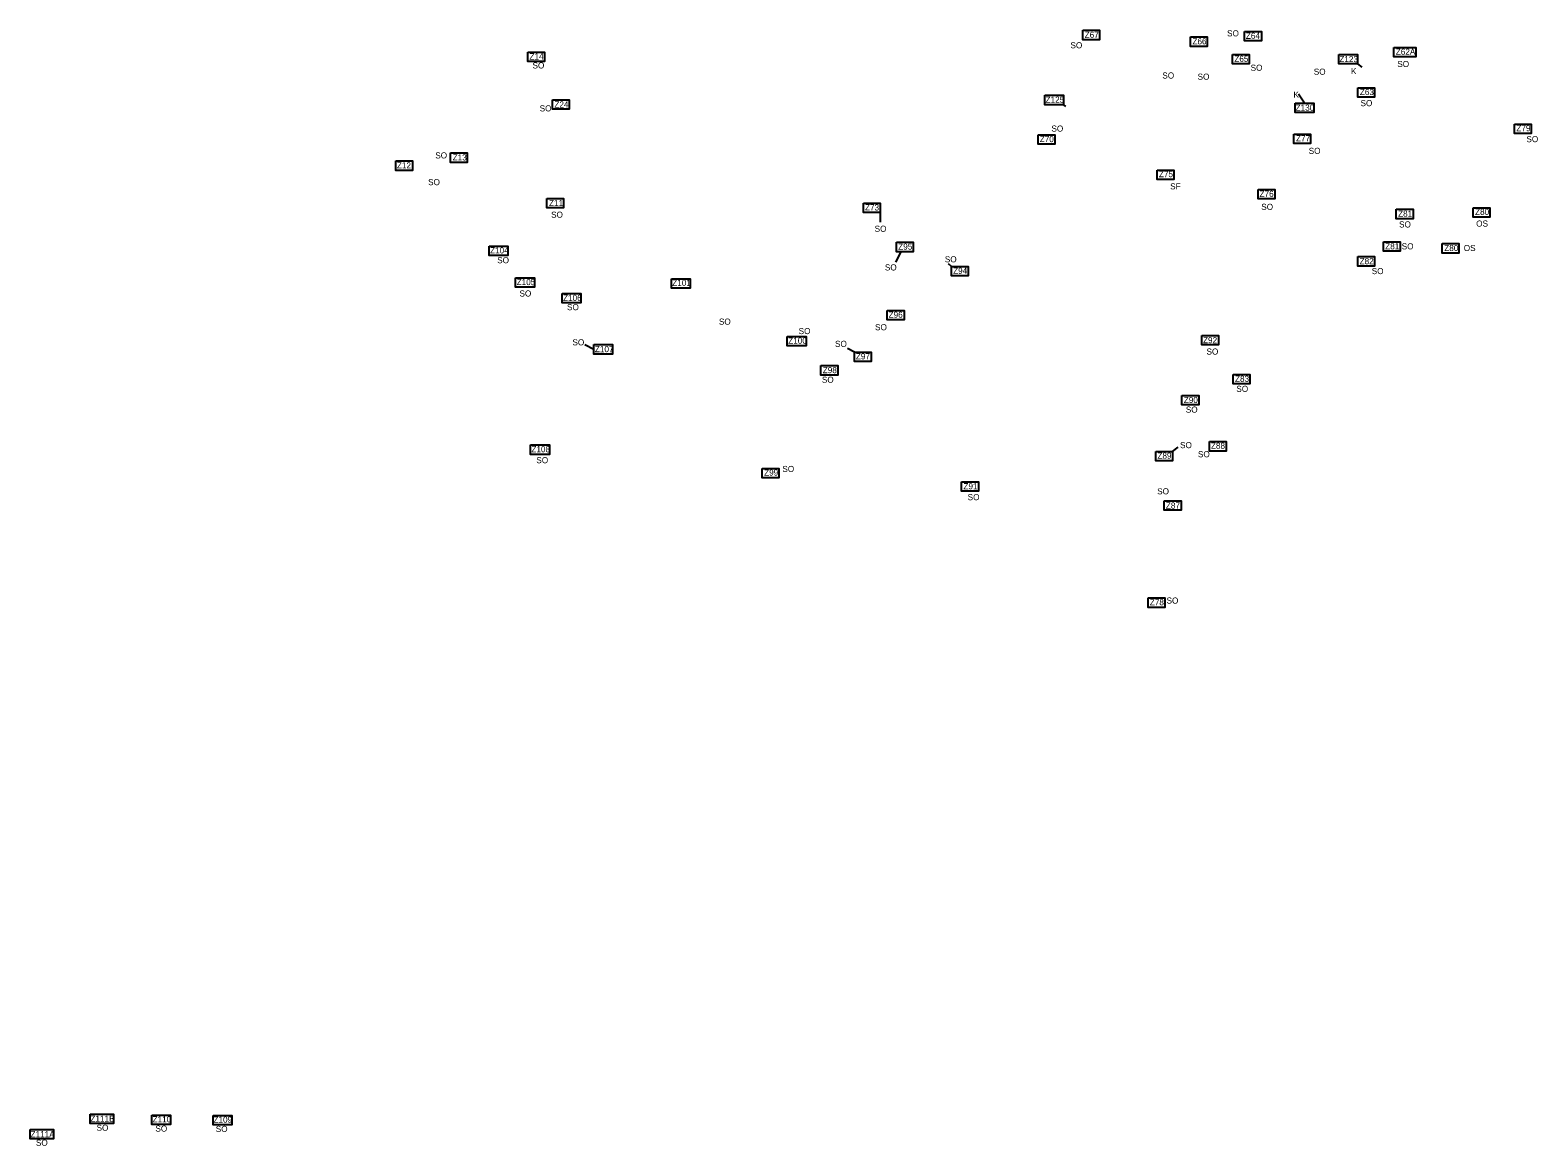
# Model space of a CAD drawing. Extents: x -443485 to -433023, y -1133480 to -1129775.
# Drawn here: x -443485 to -441021, y -1133480 to -1131657 of the extents above; entities that cross this region are included whole.
import ezdxf

# ---------------------------------------------------------------- set-up
doc = ezdxf.new("R2010")
doc.units = 0
for name, color, linetype in [('Vrstva 3', 7, 'Continuous'), ('Vrstva 4', 7, 'Continuous'), ('Vrstva 8', 7, 'Continuous')]:
    doc.layers.add(name, color=color, linetype=linetype)

msp = doc.modelspace()

# ---------------------------------------------------------------- linework, layer by layer
at = {"layer": 'Vrstva 3'}
for p, q in [((-441796.1, -1131778.7), (-441793, -1131781.3)), ((-442095.6, -1131954.7), (-442095.6, -1131970.4)), ((-442061.8, -1132018.8), (-442070.5, -1132035.8)), ((-441979.2, -1132043), (-441984, -1132038.5)), ((-442563.8, -1132178.3), (-442578.2, -1132171.1)), ((-442137.9, -1132182.9), (-442149.2, -1132176.8)), ((-441618.1, -1132344.9), (-441608.8, -1132338.2))]:
    msp.add_line(p, q, dxfattribs=at)
for points in [[(-441764.6, -1131657.1), (-441737.2, -1131657.1), (-441737.2, -1131672.5), (-441764.6, -1131672.5)], [(-441588.7, -1131668), (-441561.3, -1131668), (-441561.3, -1131683.4), (-441588.7, -1131683.4)], [(-441500.3, -1131658.8), (-441472.9, -1131658.8), (-441472.9, -1131674.2), (-441500.3, -1131674.2)], [(-442671.7, -1131692.6), (-442644.4, -1131692.6), (-442644.4, -1131708), (-442671.7, -1131708)], [(-441520.2, -1131696.6), (-441492.8, -1131696.6), (-441492.8, -1131712), (-441520.2, -1131712)], [(-441256.6, -1131685.1), (-441220.2, -1131685.1), (-441220.2, -1131700.5), (-441256.6, -1131700.5)], [(-441315.3, -1131751.1), (-441287.9, -1131751.1), (-441287.9, -1131766.5), (-441315.3, -1131766.5)], [(-442631.4, -1131770.7), (-442604, -1131770.7), (-442604, -1131786.1), (-442631.4, -1131786.1)], [(-441837.6, -1131827.9), (-441810.3, -1131827.9), (-441810.3, -1131843.3), (-441837.6, -1131843.3)], [(-441419.8, -1131826.6), (-441392.4, -1131826.6), (-441392.4, -1131842), (-441419.8, -1131842)], [(-441059.4, -1131810.2), (-441032.1, -1131810.2), (-441032.1, -1131825.6), (-441059.4, -1131825.6)], [(-442887.2, -1131870.5), (-442859.8, -1131870.5), (-442859.8, -1131885.9), (-442887.2, -1131885.9)], [(-442797.9, -1131857.5), (-442770.5, -1131857.5), (-442770.5, -1131872.9), (-442797.9, -1131872.9)], [(-441643.3, -1131885.3), (-441615.9, -1131885.3), (-441615.9, -1131900.7), (-441643.3, -1131900.7)], [(-441478.3, -1131917), (-441450.9, -1131917), (-441450.9, -1131932.4), (-441478.3, -1131932.4)], [(-442640.4, -1131931.9), (-442613, -1131931.9), (-442613, -1131947.3), (-442640.4, -1131947.3)], [(-442123, -1131939.3), (-442095.6, -1131939.3), (-442095.6, -1131954.7), (-442123, -1131954.7)], [(-441252.4, -1131949.4), (-441225, -1131949.4), (-441225, -1131964.8), (-441252.4, -1131964.8)], [(-441126.7, -1131946.9), (-441099.4, -1131946.9), (-441099.4, -1131962.3), (-441126.7, -1131962.3)], [(-442734.8, -1132009.7), (-442704, -1132009.7), (-442704, -1132025.1), (-442734.8, -1132025.1)], [(-442069.1, -1132003.4), (-442041.7, -1132003.4), (-442041.7, -1132018.8), (-442069.1, -1132018.8)], [(-441315.4, -1132026.8), (-441288, -1132026.8), (-441288, -1132042.2), (-441315.4, -1132042.2)], [(-441273.5, -1132002.7), (-441246.1, -1132002.7), (-441246.1, -1132018.1), (-441273.5, -1132018.1)], [(-441177.4, -1132005.6), (-441150, -1132005.6), (-441150, -1132021), (-441177.4, -1132021)], [(-441979.2, -1132043), (-441951.8, -1132043), (-441951.8, -1132058.4), (-441979.2, -1132058.4)], [(-442691.5, -1132061.4), (-442660.7, -1132061.4), (-442660.7, -1132076.8), (-442691.5, -1132076.8)], [(-442436.8, -1132062.9), (-442406.1, -1132062.9), (-442406.1, -1132078.3), (-442436.8, -1132078.3)], [(-442615.4, -1132087.1), (-442584.7, -1132087.1), (-442584.7, -1132102.5), (-442615.4, -1132102.5)], [(-442084.1, -1132114.6), (-442056.8, -1132114.6), (-442056.8, -1132129.9), (-442084.1, -1132129.9)], [(-442563.8, -1132170.6), (-442533.1, -1132170.6), (-442533.1, -1132186), (-442563.8, -1132186)], [(-442247.5, -1132157.2), (-442216.7, -1132157.2), (-442216.7, -1132172.6), (-442247.5, -1132172.6)], [(-441570.4, -1132155.6), (-441543.1, -1132155.6), (-441543.1, -1132171), (-441570.4, -1132171)], [(-442137.9, -1132182.9), (-442110.5, -1132182.9), (-442110.5, -1132198.2), (-442137.9, -1132198.2)], [(-442192.5, -1132204.9), (-442165.1, -1132204.9), (-442165.1, -1132220.3), (-442192.5, -1132220.3)], [(-441518.9, -1132219.3), (-441491.5, -1132219.3), (-441491.5, -1132234.7), (-441518.9, -1132234.7)], [(-441602.6, -1132253.6), (-441575.2, -1132253.6), (-441575.2, -1132269), (-441602.6, -1132269)], [(-442667.1, -1132334.4), (-442636.3, -1132334.4), (-442636.3, -1132349.8), (-442667.1, -1132349.8)], [(-441645.5, -1132344.9), (-441618.1, -1132344.9), (-441618.1, -1132360.3), (-441645.5, -1132360.3)], [(-441557.5, -1132329), (-441530.2, -1132329), (-441530.2, -1132344.4), (-441557.5, -1132344.4)], [(-442288.6, -1132372.9), (-442261.2, -1132372.9), (-442261.2, -1132388.3), (-442288.6, -1132388.3)], [(-441962.6, -1132394.5), (-441935.3, -1132394.5), (-441935.3, -1132409.9), (-441962.6, -1132409.9)], [(-441631.5, -1132425.8), (-441604.1, -1132425.8), (-441604.1, -1132441.2), (-441631.5, -1132441.2)], [(-441657.9, -1132584.5), (-441630.5, -1132584.5), (-441630.5, -1132599.9), (-441657.9, -1132599.9)], [(-443387, -1133427.6), (-443348.5, -1133427.6), (-443348.5, -1133443), (-443387, -1133443)], [(-443286.1, -1133429.5), (-443255.3, -1133429.5), (-443255.3, -1133444.9), (-443286.1, -1133444.9)], [(-443186, -1133429.7), (-443155.2, -1133429.7), (-443155.2, -1133445.1), (-443186, -1133445.1)], [(-443484.8, -1133452.9), (-443446.4, -1133452.9), (-443446.4, -1133468.3), (-443484.8, -1133468.3)]]:
    msp.add_lwpolyline(points, close=True, dxfattribs=at)
at = {"layer": 'Vrstva 8'}
for p, q in [((-441315.6, -1131712), (-441308.9, -1131717.3)), ((-441402.4, -1131775.9), (-441412, -1131761.5))]:
    msp.add_line(p, q, dxfattribs=at)
for points in [[(-441346.4, -1131696.6), (-441315.6, -1131696.6), (-441315.6, -1131712), (-441346.4, -1131712)], [(-441826.9, -1131763.3), (-441796.1, -1131763.3), (-441796.1, -1131778.7), (-441826.9, -1131778.7)], [(-441417.8, -1131775.9), (-441387.1, -1131775.9), (-441387.1, -1131791.3), (-441417.8, -1131791.3)]]:
    msp.add_lwpolyline(points, close=True, dxfattribs=at)

# ---------------------------------------------------------------- texts
at = {"layer": 'Vrstva 3'}
for s, p in [('Z67', (-441761.6, -1131669.4)), ('Z66', (-441585.5, -1131680.1)), ('Z64', (-441498.2, -1131671)), ('Z14', (-442668.9, -1131704.8)), ('Z65', (-441517, -1131708.6)), ('Z62A', (-441253.2, -1131697)), ('Z63', (-441311.9, -1131762.9)), ('Z24', (-442628.1, -1131783.2)), ('Z70', (-441835, -1131839.8)), ('Z77', (-441416.3, -1131838.6)), ('Z79', (-441056.1, -1131821.9)), ('Z12', (-442885.5, -1131882.7)), ('Z13', (-442794.4, -1131869.7)), ('Z75', (-441640.3, -1131897)), ('Z76', (-441475.8, -1131929.2)), ('Z11', (-442636.9, -1131944.2)), ('Z73', (-442120.6, -1131951.4)), ('Z81', (-441249.4, -1131961.6)), ('Z80', (-441123.6, -1131958.7)), ('Z104', (-442733.3, -1132021.6)), ('Z95', (-442066.3, -1132015.4)), ('Z81', (-441270.5, -1132014.9)), ('Z80', (-441174, -1132017.7)), ('Z94', (-441976.6, -1132054.9)), ('Z82', (-441312.3, -1132039.2)), ('Z105', (-442689.8, -1132073.4)), ('Z101', (-442435.6, -1132074.6)), ('Z106', (-442614, -1132099.2)), ('Z96', (-442082, -1132126.7)), ('Z107', (-442562, -1132182.9)), ('Z100', (-442246, -1132169)), ('Z92', (-441568.2, -1132168.2)), ('Z97', (-442135.5, -1132194.7)), ('Z98', (-442189.6, -1132217.2)), ('Z83', (-441515.9, -1132231.4)), ('Z90', (-441599.6, -1132266)), ('Z108', (-442665.7, -1132346.4)), ('Z89', (-441642.7, -1132357)), ('Z88', (-441555.3, -1132340.8)), ('Z99', (-442285.4, -1132384.6)), ('Z91', (-441959.7, -1132406.9)), ('Z87', (-441628.9, -1132438.4)), ('Z78', (-441655.1, -1132596.5)), ('Z111B', (-443386.3, -1133440.1)), ('Z110', (-443284.8, -1133441.2)), ('Z111A', (-443484.1, -1133465.5)), ('Z109', (-443185.2, -1133441.7))]:
    msp.add_text(s, height=10, dxfattribs=at).set_placement(p)
at = {"layer": 'Vrstva 4'}
for s, p in [('SO', (-441528.9, -1131667)), ('SO', (-441784.8, -1131686.5)), ('SO', (-442663.9, -1131719.4)), ('SO', (-441634.7, -1131735.9)), ('SO', (-441577.1, -1131737.8)), ('SO', (-441490.4, -1131723.2)), ('SO', (-441387.2, -1131729.7)), ('K', (-441326.3, -1131728.7)), ('SO', (-441250.7, -1131717.1)), ('SO', (-442652.2, -1131789.6)), ('K', (-441420.4, -1131767.1)), ('SO', (-441310.8, -1131781)), ('SO', (-441815.9, -1131822.6)), ('SO', (-441039.7, -1131839.8)), ('SO', (-441395.5, -1131859)), ('SO', (-442822.8, -1131866.4)), ('SO', (-442834.5, -1131910.1)), ('SF', (-441621.9, -1131917)), ('SO', (-441473, -1131950.5)), ('SO', (-442633.5, -1131963.3)), ('SO', (-442104.8, -1131986.3)), ('SO', (-441247.8, -1131979.2)), ('OS', (-441121.8, -1131977.8)), ('SO', (-441990.1, -1132036.2)), ('SO', (-441243.5, -1132015)), ('OS', (-441142.1, -1132017.7)), ('SO', (-442721.6, -1132037.6)), ('SO', (-442088.1, -1132049.4)), ('SO', (-441292.5, -1132055.4)), ('SO', (-442685.2, -1132092)), ('SO', (-442607.5, -1132114.3)), ('SO', (-442359.3, -1132138)), ('SO', (-442229, -1132153.4)), ('SO', (-442104.1, -1132147.1)), ('SO', (-442598.6, -1132171.8)), ('SO', (-442169.5, -1132174.3)), ('SO', (-441562.5, -1132186.9)), ('SO', (-442191, -1132232.9)), ('SO', (-441513.7, -1132247.8)), ('SO', (-441596.3, -1132281.7)), ('SO', (-441605.7, -1132339.7)), ('SO', (-441576.5, -1132354.6)), ('SO', (-442657.6, -1132364.3)), ('SO', (-442255.6, -1132378.7)), ('SO', (-441952.8, -1132424.7)), ('SO', (-441643.1, -1132415.2)), ('SO', (-441627.8, -1132593.7)), ('SO', (-443376.3, -1133454.9)), ('SO', (-443280.1, -1133456.3)), ('SO', (-443181.5, -1133456.9)), ('SO', (-443475.4, -1133479.4))]:
    msp.add_text(s, height=10, dxfattribs=at).set_placement(p)
at = {"layer": 'Vrstva 8'}
for s, p in [('Z123', (-441345.4, -1131709.1)), ('Z125', (-441825.5, -1131775.3)), ('Z130', (-441416.9, -1131788.4))]:
    msp.add_text(s, height=10, dxfattribs=at).set_placement(p)

doc.saveas('drawing.dxf')
